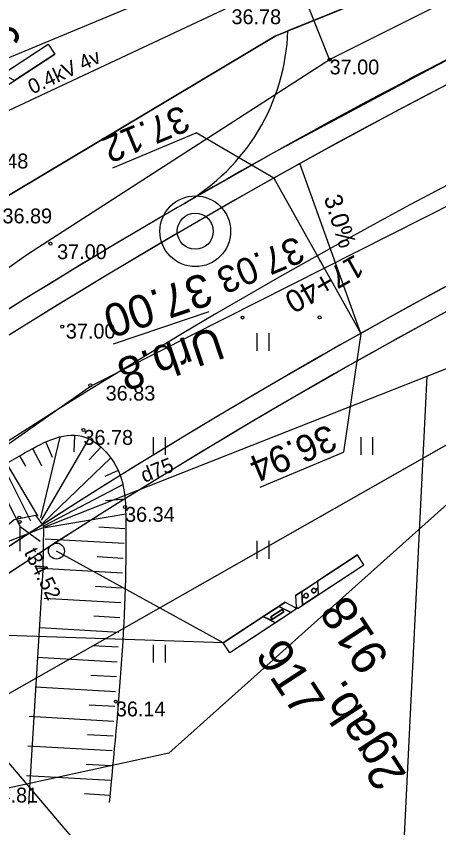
# Model space of a CAD drawing. Extents: x 469981 to 472086, y 246785 to 247785.
# Drawn here: x 470374.37 to 470388.62, y 247080.43 to 247107.78 of the extents above; entities that cross this region are included whole.
import ezdxf

# ---------------------------------------------------------------- set-up
doc = ezdxf.new("R2010")
doc.units = 0
for name, color, linetype in [('0_922', 7, 'Continuous'), ('0_Asfalta_mala', 7, 'Continuous'), ('0_Asfalta_Nomale', 7, 'Continuous'), ('0_Ruut_Braukt', 7, 'Continuous'), ('0_Ruut_nomale', 7, 'Continuous'), ('0_Ruutojums_Nobrauktuves_pieslegumi', 7, 'Continuous'), ('0_Urbumi5', 7, 'Continuous'), ('0_vertikals', 7, 'Continuous'), ('0_vertkals_cipari', 7, 'Continuous'), ('0_Ziimes', 7, 'Continuous'), ('21', 7, 'Continuous'), ('6_piketaza', 7, 'Continuous'), ('CELI_CMAL_####_####_#', 7, 'Continuous'), ('Default', 7, 'Continuous'), ('DREN_VADP_####_####_#', 7, 'Continuous'), ('DREN_VADP_KLKT_####_#', 7, 'Continuous'), ('DREN_VADP_KLKT_TKST_#', 7, 'Continuous'), ('ELEK_VADV_ZSPR_####_#', 7, 'Continuous'), ('ELEK_VADV_ZSPR_TKST_#', 7, 'Continuous'), ('HIDG_GRAV_####_####_#', 7, 'Continuous'), ('HIDT_CAUR_####_####_#', 7, 'Continuous'), ('HIDT_CAUR_####_TKST_#', 7, 'Continuous'), ('HIDT_CAUR_KONT_####_#', 7, 'Continuous'), ('HIDT_ELEM_####_####_#', 7, 'Continuous'), ('RAMI_UZMR_####_####_#', 7, 'Continuous'), ('RELJ_AATZ_####_TKST_#', 7, 'Continuous'), ('RELJ_ELEM_####_####_#', 7, 'Continuous'), ('RELJ_NOGA_####_####_#', 7, 'Continuous'), ('ROBZ_IERR_####_####_#', 7, 'Continuous'), ('ROBZ_PROJ_####_####_#', 7, 'Continuous'), ('TERT_ELEM_####_####_#', 7, 'Continuous'), ('Z_PILD_MELNS', 7, 'Continuous'), ('zogi', 7, 'Continuous')]:
    doc.layers.add(name, color=color, linetype=linetype)

# ---------------------------------------------------------------- blocks, each defined once
blk = doc.blocks.new('A$C03B17208')
at = {"layer": 'Default'}
blk.add_circle((1.418, 1.418), 0.723, dxfattribs=at)
at = {"layer": 'zogi'}
blk.add_circle((1.418, 1.418), 1.418, dxfattribs=at)

msp = doc.modelspace()

# ---------------------------------------------------------------- linework, layer by layer
at = {"layer": '0_922'}
msp.add_arc((470487.184, 246916.514), 210, 113.13829, 135.11501, dxfattribs=at)
at = {"layer": '0_Asfalta_mala'}
for radius in [213, 207]:
    msp.add_arc((470487.184, 246916.514), radius, 113.13829, 135.11501, dxfattribs=at)
at = {"layer": '0_Asfalta_Nomale'}
msp.add_line((470389.692, 247109.786), (470383.531, 247107.29), dxfattribs=at)
for centre, radius, start, end in [((470376.535, 247107.531), 7, 300.0821, 358.0241), ((470487.184, 246916.514), 206.25, 113.13829, 135.11501), ((470487.184, 246916.514), 213.75, 120.08211, 135.11501)]:
    msp.add_arc(centre, radius, start, end, dxfattribs=at)
at = {"layer": '0_Ruut_Braukt'}
for radius in [213, 207]:
    msp.add_arc((470487.184, 246916.514), radius, 113.13829, 135.11501, dxfattribs=at)
at = {"layer": '0_Ruut_nomale'}
for p, q in [((470386.256, 247104.895), (470383.795, 247103.58)), ((470382.573, 247102.911), (470379.812, 247101.339))]:
    msp.add_line(p, q, dxfattribs=at)
for points in [[(470395.782, 247109.736), (470393.165, 247108.452), (470390.364, 247107.068), (470388.366, 247106.021), (470386.256, 247104.895)], [(470383.795, 247103.58), (470383.042, 247103.178), (470382.573, 247102.911)]]:
    msp.add_lwpolyline(points, dxfattribs=at)
for radius, start, end in [(213, 113.13829, 129.44229), (207, 113.13829, 130.0782), (206.25, 113.13829, 130.16049), (213.75, 120.15409, 129.3655)]:
    msp.add_arc((470487.184, 246916.514), radius, start, end, dxfattribs=at)
at = {"layer": '0_Ruutojums_Nobrauktuves_pieslegumi'}
msp.add_line((470389.692, 247109.786), (470383.531, 247107.29), dxfattribs=at)
for centre, radius, start, end in [((470487.184, 246916.514), 213.75, 115.31612, 120.08211), ((470376.535, 247107.531), 7, 300.0821, 358.0241)]:
    msp.add_arc(centre, radius, start, end, dxfattribs=at)
at = {"layer": '0_Urbumi5'}
msp.add_lwpolyline([(470380.867, 247097.821), (470377.641, 247096.726)], dxfattribs=at)
at = {"layer": '0_vertikals'}
for p, q in [((470377.628, 247102.671), (470380.439, 247103.848)), ((470383.056, 247102.327), (470380.439, 247103.848)), ((470385.989, 247097.093), (470385.401, 247093.09)), ((470382.591, 247091.914), (470385.401, 247093.09))]:
    msp.add_line(p, q, dxfattribs=at)
msp.add_lwpolyline([(470385.989, 247097.093), (470383.93, 247102.814), (470383.056, 247102.327)], close=True, dxfattribs=at)
at = {"layer": '0_Ziimes'}
for q in [(470375.728, 247089.758), (470371.556, 247087.002)]:
    msp.add_line((470381.348, 247086.663), q, dxfattribs=at)
msp.add_circle((470375.728, 247089.758), 0.27, dxfattribs=at)
msp.add_circle((470375.728, 247089.758), 0.27, dxfattribs=at)
at = {"layer": '21'}
msp.add_arc((470487.184, 246916.514), 210, 113.13829, 135.11501, dxfattribs=at)
at = {"layer": '6_piketaza'}
msp.add_lwpolyline([(470384.645, 247099.492), (470384.401, 247099.928)], dxfattribs=at)
at = {"layer": 'CELI_CMAL_####_####_#'}
for points in [[(470207.251, 246955.004), (470220.145, 246963.116), (470261.486, 246992.424), (470276.308, 247005.858), (470296.122, 247025.635), (470312.816, 247042.969), (470330.98, 247061.836), (470346.394, 247077.324), (470364.172, 247092.272), (470374.754, 247099.764), (470384.938, 247106.322), (470390.015, 247108.873), (470395.699, 247111.348), (470409.875, 247117.262), (470415.428, 247119.375), (470428.615, 247124.712), (470444.307, 247130.298), (470466.241, 247137.389), (470487.751, 247143.859), (470509.15, 247149.677), (470533.329, 247156.368), (470558.982, 247163.161), (470583.723, 247169.81), (470606.354, 247175.581)], [(470440.723, 247107.99), (470440.084, 247118.844), (470439.302, 247119.794), (470438.459, 247120.205), (470437.434, 247120.771), (470435.683, 247121.111), (470417.849, 247114.314), (470398.184, 247106.061), (470376.912, 247095.329), (470368.488, 247089.418), (470350.85, 247073.72), (470334.429, 247056.212), (470317.045, 247039.09), (470299.359, 247021.199), (470279.758, 247002.025), (470265.741, 246988.964), (470242.76, 246971.543), (470223.686, 246958.587), (470209.766, 246949.279)], [(470384.938, 247106.322), (470384.175, 247108.251), (470382.891, 247110.447)]]:
    msp.add_lwpolyline(points, dxfattribs=at)
at = {"layer": 'DREN_VADP_####_####_#'}
msp.add_lwpolyline([(470386.032, 247051.246), (470388.222, 247095.652)], dxfattribs=at)
at = {"layer": 'DREN_VADP_KLKT_####_#'}
for points in [[(470448.006, 247137.086), (470370.723, 247104.976), (470366.142, 247103.073)], [(470374.125, 247090.092), (470375.261, 247090.541), (470388.222, 247095.652), (470406.04, 247102.681), (470426.281, 247110.664)]]:
    msp.add_lwpolyline(points, dxfattribs=at)
at = {"layer": 'ELEK_VADV_ZSPR_####_#'}
for p, q in [((470397.803, 247115.732), (470360.738, 247098.313)), ((470360.738, 247098.313), (470381.961, 247073.394))]:
    msp.add_line(p, q, dxfattribs=at)
at = {"layer": 'HIDG_GRAV_####_####_#'}
msp.add_lwpolyline([(470372.562, 247080.256), (470372.938, 247084.442), (470373.238, 247088.396), (470373.423, 247089.506), (470373.862, 247090.454), (470374.301, 247090.824), (470375.017, 247090.963), (470375.295, 247090.593), (470375.272, 247089.113), (470374.786, 247081.228)], dxfattribs=at)
at = {"layer": 'HIDT_CAUR_####_####_#'}
msp.add_line((470374.504, 247090.588), (470369.621, 247100.325), dxfattribs=at)
at = {"layer": 'HIDT_CAUR_KONT_####_#'}
msp.add_line((470374.862, 247090.767), (470369.978, 247100.505), dxfattribs=at)
at = {"layer": 'HIDT_ELEM_####_####_#'}
msp.add_lwpolyline([(470374.506, 247089.75), (470374.504, 247090.588), (470375.176, 247090.086)], dxfattribs=at)
msp.add_lwpolyline([(470374.506, 247089.75), (470374.504, 247090.588), (470375.176, 247090.086)], dxfattribs=at)
at = {"layer": 'RAMI_UZMR_####_####_#'}
msp.add_lwpolyline([(470682.857, 247179.693), (470601.924, 247155.957), (470538.749, 247139.954), (470448.7, 247112.965), (470443.256, 247108.572), (470439.042, 247107.166), (470426.399, 247105.409), (470390.93, 247093.141), (470379.516, 247082.95), (470369.859, 247080.841), (470357.567, 247068.014), (470285.914, 246993.254), (470269.057, 246978.845), (470246.406, 246963.908), (470178.978, 246918.441), (470154.395, 246901.045), (470104.604, 246871.942), (470081.833, 246858.073)], dxfattribs=at)
at = {"layer": 'RELJ_ELEM_####_####_#'}
for centre in [(470384.938, 247106.322), (470375.525, 247100.118), (470382, 247097.627), (470384.599, 247097.634), (470375.923, 247097.32), (470376.871, 247095.341), (470376.637, 247093.837), (470378.04, 247091.243), (470374.475, 247090.888), (470374.492, 247090.739), (470377.729, 247084.685)]:
    msp.add_circle(centre, 0.05, dxfattribs=at)
at = {"layer": 'RELJ_NOGA_####_####_#'}
for p, q in [((470376.331, 247093.656), (470376.316, 247093.1)), ((470375.836, 247093.592), (470375.185, 247090.881)), ((470376.816, 247093.55), (470375.211, 247090.802)), ((470375.365, 247093.428), (470375.583, 247092.917)), ((470374.915, 247093.209), (470375.219, 247092.643)), ((470377.23, 247093.275), (470376.832, 247092.826)), ((470374.48, 247092.963), (470374.678, 247092.623)), ((470377.562, 247092.902), (470375.264, 247090.696)), ((470374.048, 247092.711), (470375.087, 247090.948)), ((470377.811, 247092.469), (470377.36, 247092.266)), ((470377.975, 247091.998), (470375.317, 247090.604)), ((470378.057, 247091.505), (470377.381, 247091.45)), ((470378.065, 247091.005), (470375.343, 247090.538)), ((470378.037, 247090.506), (470377.152, 247090.557)), ((470378.008, 247090.007), (470375.347, 247090.16)), ((470377.979, 247089.508), (470377.099, 247089.558)), ((470377.951, 247089.009), (470375.023, 247089.176)), ((470377.922, 247088.509), (470377.046, 247088.56)), ((470377.893, 247088.01), (470375.317, 247088.158)), ((470377.865, 247087.511), (470376.993, 247087.561)), ((470377.836, 247087.012), (470375.165, 247087.165)), ((470377.808, 247086.513), (470376.939, 247086.562)), ((470377.779, 247086.013), (470375.074, 247086.169)), ((470377.75, 247085.514), (470376.886, 247085.564)), ((470377.722, 247085.015), (470375.007, 247085.171)), ((470377.693, 247084.516), (470376.833, 247084.565)), ((470377.664, 247084.017), (470374.803, 247084.181)), ((470377.636, 247083.518), (470376.779, 247083.567)), ((470377.607, 247083.018), (470374.759, 247083.182)), ((470377.578, 247082.519), (470376.726, 247082.568)), ((470377.55, 247082.02), (470374.715, 247082.183)), ((470377.521, 247081.521), (470376.673, 247081.57))]:
    msp.add_line(p, q, dxfattribs=at)
msp.add_spline([(470369.386, 247081.581), (470369.869, 247088.299), (470371.268, 247090.645), (470374.55, 247093.004), (470376.583, 247093.628), (470377.831, 247092.425), (470378.062, 247090.946), (470377.507, 247081.28)], degree=3, dxfattribs=at)
at = {"layer": 'ROBZ_IERR_####_####_#'}
for points in [[(470455.523, 247176.924), (470421.395, 247122.632), (470383.103, 247107.116), (470368.265, 247098.262), (470337.005, 247135.402)], [(470310.127, 246974.356), (470275.956, 246992.729), (470371.503, 247083.47), (470396.219, 247097.502), (470431.624, 247112.202), (470468.364, 247124.23), (470636.973, 247175.147), (470640.03, 247134.708)]]:
    msp.add_lwpolyline(points, dxfattribs=at)
at = {"layer": 'ROBZ_PROJ_####_####_#'}
for points in [[(471398.351, 247372.094), (471346.741, 247338.478), (471133.176, 247205.05), (471108.425, 247194.786), (471087.339, 247189.709), (471023.306, 247181.157), (470962.604, 247185.245), (470905.63, 247205.857), (470878.75, 247214.454), (470852.344, 247217.039), (470815.743, 247215.147), (470778.583, 247209.26), (470718.669, 247194.633), (470636.973, 247175.147), (470468.364, 247124.23), (470431.624, 247112.202), (470396.219, 247097.502), (470371.503, 247083.47), (470275.956, 246992.729), (470152.342, 246907.761), (470066.737, 246851.23)], [(470062.774, 246863.479), (470070.591, 246868.587), (470253.618, 246988.247), (470269.149, 247002.795), (470278.124, 247011.202), (470361.554, 247094.257), (470368.265, 247098.262), (470383.103, 247107.116), (470421.395, 247122.632), (470438.432, 247129.536), (470474.818, 247141.882), (470613.752, 247179.765), (470688.303, 247197.106)]]:
    msp.add_lwpolyline(points, dxfattribs=at)
at = {"layer": 'TERT_ELEM_####_####_#'}
for p, q in [((470382.5, 247096.5), (470382.5, 247097.1)), ((470382.9, 247096.5), (470382.9, 247097.1)), ((470379, 247093), (470379, 247093.6)), ((470379.4, 247093), (470379.4, 247093.6)), ((470386, 247093), (470386, 247093.6)), ((470386.4, 247093), (470386.4, 247093.6)), ((470382.5, 247089.5), (470382.5, 247090.1)), ((470382.9, 247089.5), (470382.9, 247090.1)), ((470379, 247086), (470379, 247086.6)), ((470379.4, 247086), (470379.4, 247086.6))]:
    msp.add_line(p, q, dxfattribs=at)
at = {"layer": 'Z_PILD_MELNS'}
for p, q in [((470373.205, 247105.373), (470375.451, 247106.843)), ((470373.584, 247105.143), (470375.67, 247106.508)), ((470383.792, 247088.26), (470385.878, 247089.626)), ((470383.852, 247087.821), (470386.097, 247089.292)), ((470384.524, 247088.74), (470384.55, 247088.279)), ((470383.792, 247088.26), (470383.814, 247087.879)), ((470384.002, 247088.397), (470384.027, 247087.936)), ((470383.434, 247088.029), (470381.348, 247086.663)), ((470383.225, 247087.892), (470383.637, 247087.684)), ((470383.434, 247088.029), (470383.775, 247087.857)), ((470383.775, 247087.857), (470383.812, 247087.8)), ((470383.814, 247087.879), (470383.851, 247087.822)), ((470383.813, 247087.799), (470381.568, 247086.328)), ((470382.702, 247087.549), (470383.115, 247087.341))]:
    msp.add_line(p, q, dxfattribs=at)
for points in [[(470374.316, 247105.622), (470373.904, 247105.831), (470375.451, 247106.843), (470375.67, 247106.508)], [(470384.524, 247088.74), (470384.55, 247088.279), (470386.097, 247089.292), (470385.878, 247089.626)], [(470384.027, 247087.936), (470384.015, 247088.167), (470384.083, 247088.211), (470384.086, 247088.206), (470384.092, 247088.2), (470384.099, 247088.193), (470384.106, 247088.189), (470384.114, 247088.184), (470384.122, 247088.181), (470384.129, 247088.179), (470384.14, 247088.178), (470384.153, 247088.178), (470384.164, 247088.18), (470384.176, 247088.184), (470384.187, 247088.19), (470384.195, 247088.197), (470384.202, 247088.203), (470384.208, 247088.211), (470384.213, 247088.22), (470384.217, 247088.229), (470384.219, 247088.238), (470384.22, 247088.248), (470384.22, 247088.254), (470384.22, 247088.261), (470384.219, 247088.268), (470384.216, 247088.276), (470384.213, 247088.285), (470384.208, 247088.294), (470384.203, 247088.3), (470384.198, 247088.306), (470384.191, 247088.312), (470384.183, 247088.317), (470384.176, 247088.321), (470384.169, 247088.323), (470384.162, 247088.326), (470384.155, 247088.327), (470384.145, 247088.327), (470384.138, 247088.327), (470384.128, 247088.326), (470384.12, 247088.323), (470384.113, 247088.32), (470384.108, 247088.318), (470384.102, 247088.314), (470384.096, 247088.309), (470384.091, 247088.305), (470384.086, 247088.299), (470384.081, 247088.291), (470384.076, 247088.281), (470384.072, 247088.268), (470384.07, 247088.254), (470384.071, 247088.241), (470384.075, 247088.226), (470384.081, 247088.213), (470384.083, 247088.211), (470384.015, 247088.167), (470384.003, 247088.399), (470384.524, 247088.74), (470384.537, 247088.509), (470384.47, 247088.463), (470384.467, 247088.468), (470384.462, 247088.474), (470384.457, 247088.48), (470384.452, 247088.484), (470384.446, 247088.488), (470384.441, 247088.49), (470384.436, 247088.493), (470384.43, 247088.495), (470384.424, 247088.497), (470384.418, 247088.498), (470384.412, 247088.498), (470384.407, 247088.499), (470384.399, 247088.498), (470384.392, 247088.497), (470384.384, 247088.495), (470384.376, 247088.492), (470384.37, 247088.489), (470384.364, 247088.485), (470384.358, 247088.481), (470384.354, 247088.477), (470384.35, 247088.472), (470384.345, 247088.466), (470384.34, 247088.458), (470384.336, 247088.448), (470384.333, 247088.439), (470384.332, 247088.43), (470384.332, 247088.422), (470384.332, 247088.413), (470384.334, 247088.404), (470384.337, 247088.395), (470384.341, 247088.387), (470384.345, 247088.381), (470384.35, 247088.374), (470384.356, 247088.369), (470384.36, 247088.365), (470384.366, 247088.36), (470384.375, 247088.356), (470384.383, 247088.353), (470384.389, 247088.351), (470384.398, 247088.349), (470384.404, 247088.349), (470384.415, 247088.349), (470384.426, 247088.351), (470384.437, 247088.355), (470384.447, 247088.36), (470384.458, 247088.369), (470384.466, 247088.378), (470384.472, 247088.386), (470384.476, 247088.396), (470384.48, 247088.407), (470384.481, 247088.415), (470384.482, 247088.424), (470384.481, 247088.435), (470384.479, 247088.444), (470384.475, 247088.454), (470384.47, 247088.463), (470384.537, 247088.509), (470384.55, 247088.279)], [(470383.792, 247088.26), (470383.814, 247087.879), (470383.851, 247087.822), (470384.027, 247087.936), (470384.002, 247088.397)], [(470383.225, 247087.892), (470383.637, 247087.684), (470383.115, 247087.341), (470382.908, 247087.445), (470383.015, 247087.456), (470383.391, 247087.703), (470383.336, 247087.786), (470382.96, 247087.54), (470383.015, 247087.456), (470382.908, 247087.445), (470382.702, 247087.549)], [(470383.434, 247088.029), (470383.775, 247087.857), (470383.812, 247087.8), (470383.637, 247087.684), (470383.225, 247087.892)], [(470383.336, 247087.786), (470383.391, 247087.703), (470383.015, 247087.456), (470382.96, 247087.54)], [(470382.702, 247087.549), (470383.115, 247087.341), (470381.568, 247086.328), (470381.348, 247086.663)]]:
    msp.add_lwpolyline(points, close=True, dxfattribs=at)
for points in [[(470383.792, 247088.26), (470383.814, 247087.879), (470383.851, 247087.822)], [(470383.434, 247088.029), (470383.775, 247087.857), (470383.812, 247087.8)]]:
    msp.add_lwpolyline(points, dxfattribs=at)
for centre in [(470384.407, 247088.424), (470384.145, 247088.252)]:
    msp.add_circle(centre, 0.075, dxfattribs=at)

# ---------------------------------------------------------------- block references
at = {"layer": '0_Urbumi5', "xscale": 0.8410063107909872, "yscale": 0.8410063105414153, "rotation": 16.267799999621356}
msp.add_blockref('A$C03B17208', (470379.598, 247099.056), dxfattribs=at)

# ---------------------------------------------------------------- texts
at = {"layer": '0_Urbumi5'}
for s, p in [('37.00', (470380.734, 247099.161)), ('Urb.8', (470381.125, 247097.342))]:
    msp.add_text(s, height=1.11, rotation=198.7511, dxfattribs=at).set_placement(p)
at = {"layer": '0_vertkals_cipari'}
for s, height, rotation, p in [('37.12', 0.9, 202.7111, (470379.963, 247104.804)), ('3.0%', 0.5993, 287.4067, (470384.737, 247101.664)), ('37.03', 0.9, 202.7111, (470383.831, 247100.389)), ('36.94', 0.9, 202.7111, (470384.925, 247094.046))]:
    msp.add_text(s, height=height, rotation=rotation, dxfattribs=at).set_placement(p)
at = {"layer": '0_Ziimes'}
for s, rotation, p in [('917', 123.195, (470374.613, 247106.911)), ('918', 123.2141, (470386.979, 247086.143)), ('917', 303.2141, (470382.406, 247086.261)), ('2gab.', 123.2141, (470387.556, 247082.213))]:
    msp.add_text(s, height=1.1813, rotation=rotation, dxfattribs=at).set_placement(p)
at = {"layer": '6_piketaza'}
msp.add_text('17+40', height=0.75, rotation=209.2659, dxfattribs=at).set_placement((470385.808, 247099.771))
at = {"layer": 'DREN_VADP_KLKT_TKST_#'}
msp.add_text('d75', height=0.5, rotation=21.525, dxfattribs=at).set_placement((470378.687, 247092.053))
at = {"layer": 'ELEK_VADV_ZSPR_TKST_#'}
msp.add_text('0.4kV 4v', height=0.5, rotation=25.1716, dxfattribs=at).set_placement((470374.914, 247105.141))
at = {"layer": 'HIDT_CAUR_####_TKST_#'}
msp.add_text('t34.52', height=0.5, rotation=296.6335, dxfattribs=at).set_placement((470374.622, 247089.713))
at = {"layer": 'RELJ_AATZ_####_TKST_#'}
for s, p in [('36.78', (470381.629, 247107.515)), ('37.00', (470384.938, 247105.822)), ('36.48', (470373.105, 247102.652)), ('36.89', (470373.907, 247100.802)), ('37.00', (470375.749, 247099.596)), ('37.00', (470376.043, 247096.92)), ('36.83', (470377.386, 247094.829)), ('36.78', (470376.637, 247093.337)), ('36.34', (470378.04, 247090.743)), ('36.14', (470377.729, 247084.185)), ('34.81', (470373.435, 247081.282))]:
    msp.add_text(s, height=0.5, dxfattribs=at).set_placement(p)

doc.saveas('drawing.dxf')
